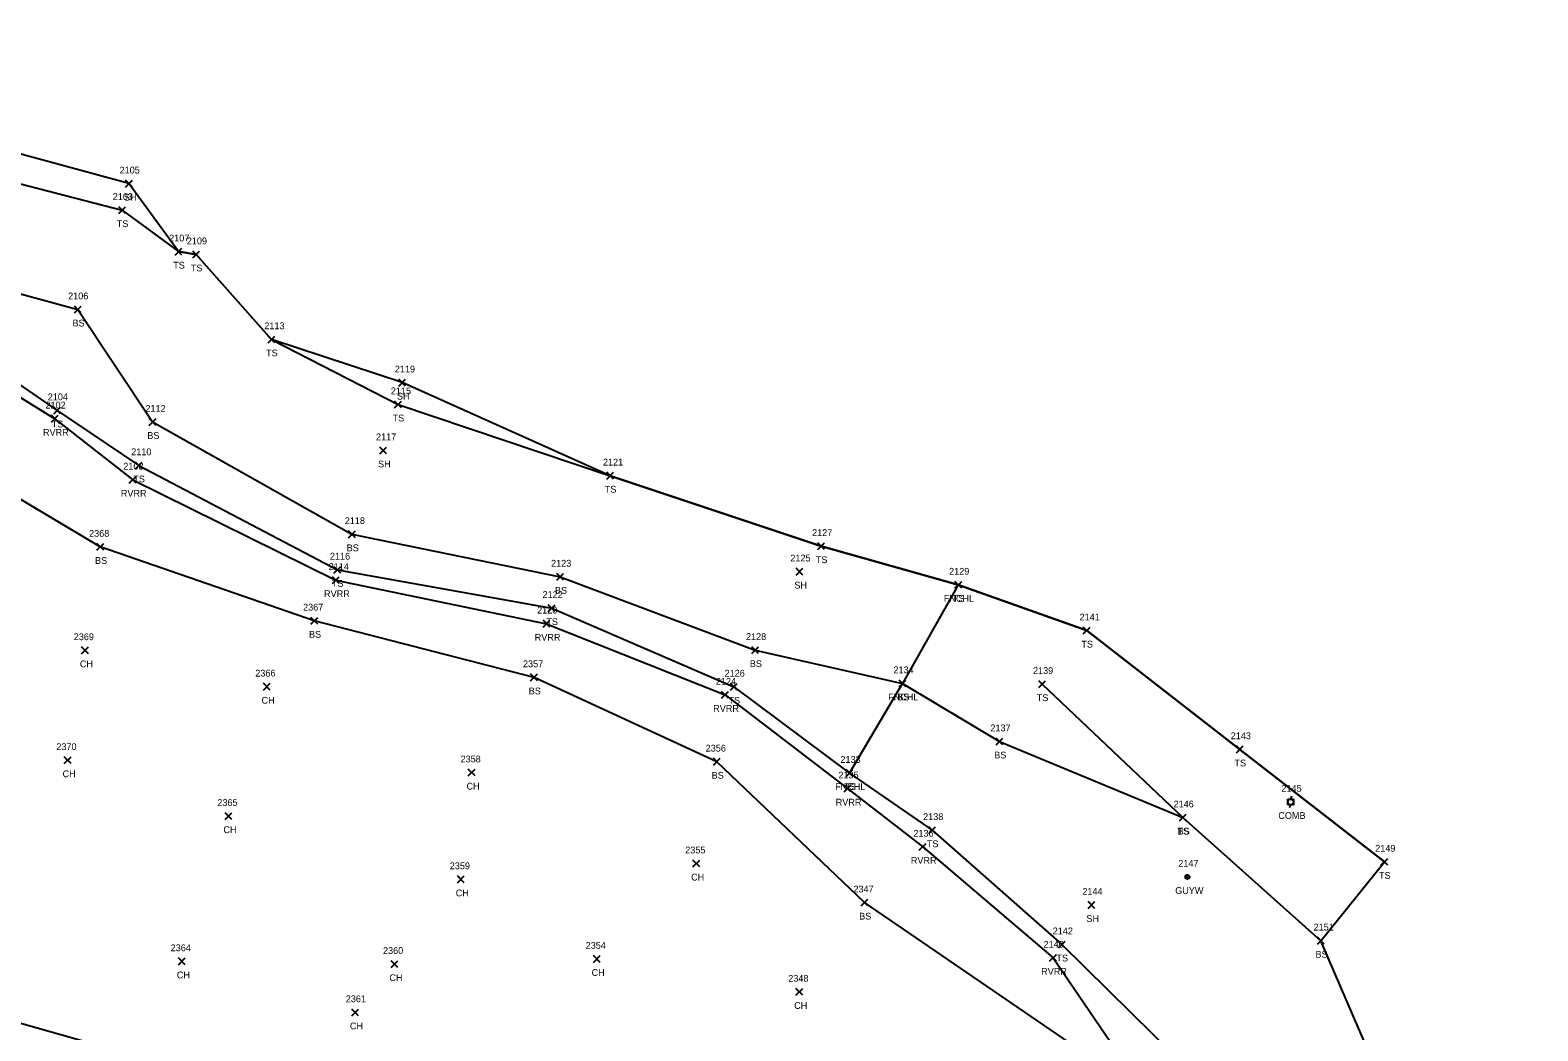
# Model space of a CAD drawing. Extents: x 1509053 to 1511576, y 400838 to 402572.
# Drawn here: x 1509430.5 to 1509874.8, y 402235 to 402530 of the extents above; entities that cross this region are included whole.
import ezdxf

# ---------------------------------------------------------------- set-up
doc = ezdxf.new("R2010")
doc.units = 0
for name, color, linetype in [('L_A', 7, 'Continuous'), ('L_I', 7, 'Continuous'), ('L_TIC', 7, 'Continuous'), ('LAWE', 7, 'Continuous'), ('LELB', 7, 'Continuous'), ('LFNC', 7, 'Continuous'), ('LSOGP', 7, 'Continuous'), ('U_A', 7, 'Continuous'), ('U_I', 7, 'Continuous'), ('UP', 7, 'Continuous'), ('UPGW', 7, 'Continuous')]:
    doc.layers.add(name, color=color, linetype=linetype)

msp = doc.modelspace()

# ---------------------------------------------------------------- linework, layer by layer
at = {"layer": 'L_TIC'}
for points in [[(1509458.59, 402483.75), (1509460.59, 402485.75)], [(1509460.59, 402483.75), (1509458.59, 402485.75)], [(1509456.58, 402475.95), (1509458.58, 402477.95)], [(1509458.58, 402475.95), (1509456.58, 402477.95)], [(1509473.2, 402463.72), (1509475.2, 402465.72)], [(1509475.2, 402463.72), (1509473.2, 402465.72)], [(1509478.41, 402462.89), (1509480.41, 402464.89)], [(1509480.41, 402462.89), (1509478.41, 402464.89)], [(1509443.49, 402446.66), (1509445.49, 402448.66)], [(1509445.49, 402446.66), (1509443.49, 402448.66)], [(1509500.59, 402437.85), (1509502.59, 402439.85)], [(1509502.59, 402437.85), (1509500.59, 402439.85)], [(1509539.07, 402425.11), (1509541.07, 402427.11)], [(1509541.07, 402425.11), (1509539.07, 402427.11)], [(1509537.87, 402418.67), (1509539.87, 402420.67)], [(1509539.87, 402418.67), (1509537.87, 402420.67)], [(1509436.74, 402414.48), (1509438.74, 402416.48)], [(1509438.74, 402414.48), (1509436.74, 402416.48)], [(1509437.42, 402416.91), (1509439.42, 402418.91)], [(1509439.42, 402416.91), (1509437.42, 402418.91)], [(1509465.55, 402413.51), (1509467.55, 402415.51)], [(1509467.55, 402413.51), (1509465.55, 402415.51)], [(1509533.51, 402405.13), (1509535.51, 402407.13)], [(1509535.51, 402405.13), (1509533.51, 402407.13)], [(1509461.46, 402400.71), (1509463.46, 402402.71)], [(1509463.46, 402400.71), (1509461.46, 402402.71)], [(1509459.68, 402396.47), (1509461.68, 402398.47)], [(1509461.68, 402396.47), (1509459.68, 402398.47)], [(1509600.4, 402397.68), (1509602.4, 402399.68)], [(1509602.4, 402397.68), (1509600.4, 402399.68)], [(1509524.3, 402380.41), (1509526.3, 402382.41)], [(1509526.3, 402380.41), (1509524.3, 402382.41)], [(1509450.14, 402376.68), (1509452.14, 402378.68)], [(1509452.14, 402376.68), (1509450.14, 402378.68)], [(1509662.58, 402376.9), (1509664.58, 402378.9)], [(1509664.58, 402376.9), (1509662.58, 402378.9)], [(1509519.99, 402369.94), (1509521.99, 402371.94)], [(1509521.99, 402369.94), (1509519.99, 402371.94)], [(1509656.17, 402369.4), (1509658.17, 402371.4)], [(1509658.17, 402369.4), (1509656.17, 402371.4)], [(1509519.56, 402366.88), (1509521.56, 402368.88)], [(1509521.56, 402366.88), (1509519.56, 402368.88)], [(1509585.66, 402367.87), (1509587.66, 402369.87)], [(1509587.66, 402367.87), (1509585.66, 402369.87)], [(1509702.97, 402365.5), (1509704.97, 402367.5)], [(1509704.97, 402365.5), (1509702.97, 402367.5)], [(1509702.97, 402365.5), (1509704.97, 402367.5)], [(1509704.97, 402365.5), (1509702.97, 402367.5)], [(1509583.16, 402358.65), (1509585.16, 402360.65)], [(1509585.16, 402358.65), (1509583.16, 402360.65)], [(1509513.2, 402354.92), (1509515.2, 402356.92)], [(1509515.2, 402354.92), (1509513.2, 402356.92)], [(1509581.65, 402354.05), (1509583.65, 402356.05)], [(1509583.65, 402354.05), (1509581.65, 402356.05)], [(1509740.81, 402352.02), (1509742.81, 402354.02)], [(1509742.81, 402352.02), (1509740.81, 402354.02)], [(1509445.62, 402346.2), (1509447.62, 402348.2)], [(1509447.62, 402346.2), (1509445.62, 402348.2)], [(1509643.11, 402346.26), (1509645.11, 402348.26)], [(1509645.11, 402346.26), (1509643.11, 402348.26)], [(1509577.95, 402338.23), (1509579.95, 402340.23)], [(1509579.95, 402338.23), (1509577.95, 402340.23)], [(1509499.18, 402335.48), (1509501.18, 402337.48)], [(1509501.18, 402335.48), (1509499.18, 402337.48)], [(1509636.85, 402335.46), (1509638.85, 402337.46)], [(1509638.85, 402335.46), (1509636.85, 402337.46)], [(1509686.55, 402336.45), (1509688.55, 402338.45)], [(1509688.55, 402336.45), (1509686.55, 402338.45)], [(1509686.55, 402336.45), (1509688.55, 402338.45)], [(1509688.55, 402336.45), (1509686.55, 402338.45)], [(1509686.55, 402336.45), (1509688.55, 402338.45)], [(1509688.55, 402336.45), (1509686.55, 402338.45)], [(1509727.69, 402336.24), (1509729.69, 402338.24)], [(1509729.69, 402336.24), (1509727.69, 402338.24)], [(1509634.23, 402333.07), (1509636.23, 402335.07)], [(1509636.23, 402333.07), (1509634.23, 402335.07)], [(1509715.12, 402319.34), (1509717.12, 402321.34)], [(1509717.12, 402319.34), (1509715.12, 402321.34)], [(1509785.94, 402317), (1509787.94, 402319.01)], [(1509787.94, 402317), (1509785.94, 402319.01)], [(1509440.53, 402313.81), (1509442.53, 402315.81)], [(1509442.53, 402313.81), (1509440.53, 402315.81)], [(1509631.84, 402313.37), (1509633.84, 402315.37)], [(1509633.84, 402313.37), (1509631.84, 402315.37)], [(1509559.56, 402310.17), (1509561.56, 402312.17)], [(1509561.56, 402310.17), (1509559.56, 402312.17)], [(1509670.92, 402310.04), (1509672.92, 402312.04)], [(1509672.92, 402310.04), (1509670.92, 402312.04)], [(1509670.92, 402310.04), (1509672.92, 402312.04)], [(1509672.92, 402310.04), (1509670.92, 402312.04)], [(1509670.34, 402305.45), (1509672.33, 402307.45)], [(1509672.33, 402305.45), (1509670.34, 402307.45)], [(1509487.94, 402297.33), (1509489.93, 402299.33)], [(1509489.93, 402297.33), (1509487.94, 402299.33)], [(1509769.14, 402296.9), (1509771.14, 402298.9)], [(1509771.14, 402296.9), (1509769.14, 402298.9)], [(1509769.14, 402296.9), (1509771.14, 402298.9)], [(1509771.14, 402296.9), (1509769.14, 402298.9)], [(1509695.29, 402293.19), (1509697.29, 402295.19)], [(1509697.29, 402293.19), (1509695.29, 402295.19)], [(1509692.47, 402288.28), (1509694.47, 402290.28)], [(1509694.47, 402288.28), (1509692.47, 402290.28)], [(1509625.76, 402283.35), (1509627.76, 402285.35)], [(1509627.76, 402283.35), (1509625.76, 402285.35)], [(1509828.53, 402283.86), (1509830.53, 402285.86)], [(1509830.53, 402283.86), (1509828.53, 402285.86)], [(1509556.39, 402278.69), (1509558.39, 402280.69)], [(1509558.39, 402278.69), (1509556.39, 402280.69)], [(1509675.33, 402271.85), (1509677.33, 402273.85)], [(1509677.33, 402271.85), (1509675.33, 402273.85)], [(1509742.22, 402271.14), (1509744.22, 402273.14)], [(1509744.22, 402271.14), (1509742.22, 402273.14)], [(1509733.48, 402259.5), (1509735.48, 402261.5)], [(1509735.48, 402259.5), (1509733.48, 402261.5)], [(1509809.8, 402260.62), (1509811.8, 402262.62)], [(1509811.8, 402260.62), (1509809.8, 402262.62)], [(1509474.19, 402254.52), (1509476.19, 402256.52)], [(1509476.19, 402254.52), (1509474.19, 402256.52)], [(1509536.84, 402253.72), (1509538.84, 402255.72)], [(1509538.84, 402253.72), (1509536.84, 402255.72)], [(1509596.43, 402255.24), (1509598.43, 402257.24)], [(1509598.43, 402255.24), (1509596.43, 402257.24)], [(1509730.88, 402255.56), (1509732.88, 402257.56)], [(1509732.88, 402255.56), (1509730.88, 402257.56)], [(1509656.12, 402245.53), (1509658.12, 402247.53)], [(1509658.12, 402245.53), (1509656.12, 402247.53)], [(1509525.21, 402239.48), (1509527.21, 402241.48)], [(1509527.21, 402239.48), (1509525.21, 402241.48)]]:
    msp.add_lwpolyline(points, dxfattribs=at)
at = {"layer": 'LAWE'}
msp.add_lwpolyline([(1509123.74, 402492.84), (1509257.15, 402479.28), (1509295.46, 402474.2), (1509323.52, 402463.27), (1509340.74, 402459.51), (1509387.7, 402446.48), (1509437.74, 402415.48), (1509460.68, 402397.47), (1509520.56, 402367.88), (1509582.65, 402355.05), (1509635.23, 402334.07), (1509671.33, 402306.45), (1509693.48, 402289.28), (1509731.88, 402256.56), (1509764.07, 402209.44), (1509800.56, 402171.69), (1509807.78, 402147.71), (1509842.98, 402079.8), (1509863.82, 402015.71), (1509885.9, 401967.01)], dxfattribs=at)
at = {"layer": 'LELB'}
for points in [[(1509115.54, 402530), (1509210.25, 402526.55), (1509259.04, 402514.59), (1509304.29, 402509.73), (1509334.97, 402505.2), (1509343.55, 402508.97), (1509356.02, 402506.81), (1509405.08, 402490.51), (1509457.58, 402476.95), (1509474.2, 402464.72), (1509479.41, 402463.89), (1509501.59, 402438.85), (1509538.87, 402419.67), (1509601.4, 402398.68), (1509663.58, 402377.9), (1509703.97, 402366.5), (1509741.81, 402353.02), (1509786.94, 402318.01), (1509829.53, 402284.86)], [(1510159.39, 401957.43), (1510109.97, 401933.78), (1510073.83, 401925.83), (1510030.04, 401920.72), (1509978.38, 401922.31), (1509938.9, 401925.26), (1509910.2, 401929.61), (1509860.63, 401969.45), (1509838.12, 402012.73), (1509801.23, 402094.39), (1509783.45, 402152.2), (1509742.56, 402227.61), (1509676.33, 402272.85), (1509632.84, 402314.37), (1509578.95, 402339.23), (1509514.2, 402355.92), (1509451.14, 402377.68), (1509400.45, 402407.85), (1509346.01, 402449.55), (1509331.23, 402458.28), (1509283.72, 402454.96), (1509188.27, 402469.29), (1509186.96, 402469.12), (1509142.12, 402468.65)], [(1509347.55, 402467.93), (1509400.56, 402459.64), (1509444.49, 402447.66), (1509466.55, 402414.51), (1509525.3, 402381.4), (1509586.66, 402368.88), (1509644.11, 402347.26), (1509687.55, 402337.45), (1509716.12, 402320.34), (1509770.15, 402297.9), (1509810.8, 402261.62)], [(1509342.35, 402460.5), (1509388.98, 402451.84), (1509438.42, 402417.91), (1509462.47, 402401.71), (1509520.99, 402370.94), (1509584.16, 402359.65), (1509637.85, 402336.46), (1509671.92, 402311.04), (1509696.29, 402294.18), (1509734.49, 402260.5), (1509774.99, 402220.64)], [(1509893.6, 401622.33), (1509860.64, 401660.7), (1509835.46, 401719.88), (1509820.45, 401775.67), (1509804.55, 401821.18), (1509793.58, 401877.47), (1509769.39, 401921.13), (1509750.31, 401995.31), (1509714.67, 402043.06), (1509675.87, 402101.28), (1509636.96, 402136.16), (1509603.47, 402183.37), (1509565.38, 402200.63), (1509506.19, 402219.72), (1509454.31, 402229.61), (1509409.3, 402242.42), (1509343.87, 402268.78), (1509286.85, 402299.31), (1509229.32, 402329.05), (1509168.38, 402334.88), (1509111.42, 402354.71)], [(1509728.69, 402337.24), (1509770.15, 402297.9)]]:
    msp.add_lwpolyline(points, dxfattribs=at)
at = {"layer": 'LFNC'}
for points in [[(1509703.97, 402366.5), (1509687.55, 402337.45)], [(1509671.92, 402311.04), (1509687.55, 402337.45)]]:
    msp.add_lwpolyline(points, dxfattribs=at)
at = {"layer": 'LSOGP'}
msp.add_lwpolyline([(1509886.95, 402120.34), (1509847.82, 402175.09), (1509849.39, 402190.96), (1509846.35, 402196.04), (1509831.65, 402213.38), (1509810.8, 402261.62), (1509829.53, 402284.86), (1509786.94, 402318.01), (1509741.81, 402353.02), (1509703.97, 402366.5), (1509663.58, 402377.9), (1509601.4, 402398.68), (1509540.06, 402426.11), (1509501.59, 402438.85), (1509479.41, 402463.89), (1509474.2, 402464.72), (1509459.59, 402484.75), (1509407.76, 402498.88)], dxfattribs=at)
at = {"layer": 'UP'}
for p, q in [((1509802.15, 402304.18), (1509801.9, 402303.35)), ((1509801.06, 402301.68), (1509801.06, 402303.35)), ((1509801.06, 402303.35), (1509802.73, 402303.35)), ((1509802.73, 402301.68), (1509801.06, 402301.68)), ((1509801.65, 402300.85), (1509801.9, 402301.68)), ((1509801.9, 402302.52), (1509801.9, 402302.52)), ((1509802.73, 402303.35), (1509802.73, 402301.68))]:
    msp.add_line(p, q, dxfattribs=at)
msp.add_circle((1509801.9, 402302.52), 0.833, dxfattribs=at)
at = {"layer": 'UPGW'}
for radius in [0.625, 0.0833]:
    msp.add_circle((1509771.5, 402280.41), radius, dxfattribs=at)

# ---------------------------------------------------------------- texts
at = {"layer": 'L_A'}
for s, p in [('SH', (1509458.08, 402479.75)), ('TS', (1509455.99, 402471.95)), ('TS', (1509472.61, 402459.72)), ('TS', (1509477.82, 402458.89)), ('BS', (1509442.93, 402442.66)), ('TS', (1509500, 402433.85)), ('SH', (1509538.55, 402421.11)), ('TS', (1509537.28, 402414.67)), ('RVRR', (1509434.25, 402410.48)), ('TS', (1509436.83, 402412.91)), ('BS', (1509464.99, 402409.51)), ('SH', (1509533, 402401.12)), ('TS', (1509460.87, 402396.71)), ('RVRR', (1509457.19, 402392.47)), ('TS', (1509599.81, 402393.68)), ('BS', (1509523.74, 402376.41)), ('BS', (1509449.58, 402372.68)), ('TS', (1509661.99, 402372.9)), ('TS', (1509519.4, 402365.94)), ('SH', (1509655.66, 402365.4)), ('RVRR', (1509517.08, 402362.88)), ('BS', (1509585.1, 402363.87)), ('FNCHL', (1509699.72, 402361.5)), ('TS', (1509702.38, 402361.5)), ('TS', (1509582.57, 402354.65)), ('BS', (1509512.64, 402350.92)), ('RVRR', (1509579.16, 402350.05)), ('TS', (1509740.22, 402348.02)), ('CH', (1509445.11, 402342.2)), ('BS', (1509642.55, 402342.26)), ('BS', (1509577.39, 402334.23)), ('CH', (1509498.66, 402331.48)), ('RVRR', (1509631.75, 402329.07)), ('TS', (1509636.26, 402331.46)), ('FNCHL', (1509683.3, 402332.45)), ('FNCHL', (1509683.3, 402332.45)), ('BS', (1509685.99, 402332.45)), ('TS', (1509727.1, 402332.24)), ('BS', (1509714.56, 402315.34)), ('TS', (1509785.35, 402313)), ('CH', (1509440.02, 402309.81)), ('BS', (1509631.28, 402309.37)), ('CH', (1509559.05, 402306.17)), ('FNCHL', (1509667.67, 402306.04)), ('TS', (1509670.33, 402306.04)), ('RVRR', (1509667.85, 402301.45)), ('CH', (1509487.42, 402293.33)), ('TS', (1509694.7, 402289.18)), ('TS', (1509768.55, 402292.9)), ('BS', (1509768.59, 402292.9)), ('RVRR', (1509689.99, 402284.28)), ('CH', (1509625.24, 402279.35)), ('TS', (1509827.94, 402279.86)), ('CH', (1509555.88, 402274.69)), ('BS', (1509674.77, 402267.85)), ('SH', (1509741.71, 402267.14)), ('TS', (1509732.89, 402255.5)), ('BS', (1509809.24, 402256.62)), ('CH', (1509473.68, 402250.52)), ('CH', (1509536.33, 402249.72)), ('CH', (1509595.92, 402251.24)), ('RVRR', (1509728.39, 402251.56)), ('CH', (1509655.61, 402241.53)), ('CH', (1509524.7, 402235.48))]:
    msp.add_text(s, height=2, dxfattribs=at).set_placement(p)
at = {"layer": 'L_I'}
for s, p in [('2105', (1509456.82, 402487.75)), ('2103', (1509454.81, 402479.95)), ('2107', (1509471.43, 402467.72)), ('2109', (1509476.63, 402466.89)), ('2106', (1509441.66, 402450.66)), ('2113', (1509499.47, 402441.85)), ('2119', (1509537.93, 402429.11)), ('2115', (1509536.75, 402422.67)), ('2102', (1509434.97, 402418.48)), ('2104', (1509435.65, 402420.91)), ('2112', (1509464.43, 402417.51)), ('2117', (1509532.39, 402409.12)), ('2110', (1509460.25, 402404.71)), ('2108', (1509457.91, 402400.47)), ('2121', (1509599.27, 402401.68)), ('2118', (1509523.17, 402384.41)), ('2368', (1509447.83, 402380.68)), ('2127', (1509660.88, 402380.9)), ('2116', (1509518.81, 402373.94)), ('2125', (1509654.48, 402373.4)), ('2114', (1509518.44, 402370.88)), ('2123', (1509583.97, 402371.87)), ('2129', (1509701.27, 402369.5)), ('2129', (1509701.27, 402369.5)), ('2122', (1509581.47, 402362.65)), ('2367', (1509510.89, 402358.92)), ('2120', (1509579.87, 402358.05)), ('2141', (1509739.69, 402356.02)), ('2369', (1509443.31, 402350.2)), ('2128', (1509641.42, 402350.26)), ('2357', (1509575.69, 402342.23)), ('2366', (1509496.81, 402339.48)), ('2126', (1509635.1, 402339.46)), ('2134', (1509684.86, 402340.45)), ('2134', (1509684.86, 402340.45)), ('2134', (1509684.86, 402340.45)), ('2139', (1509725.99, 402340.24)), ('2124', (1509632.54, 402337.07)), ('2137', (1509713.43, 402323.34)), ('2143', (1509784.25, 402321.01)), ('2370', (1509438.19, 402317.81)), ('2356', (1509629.53, 402317.37)), ('2358', (1509557.3, 402314.17)), ('2133', (1509669.23, 402314.04)), ('2133', (1509669.23, 402314.04)), ('2135', (1509668.64, 402309.45)), ('2365', (1509485.63, 402301.33)), ('2146', (1509767.4, 402300.9)), ('2146', (1509767.4, 402300.9)), ('2138', (1509693.6, 402297.18)), ('2136', (1509690.73, 402292.28)), ('2355', (1509623.5, 402287.35)), ('2149', (1509826.83, 402287.86)), ('2359', (1509554.12, 402282.69)), ('2347', (1509673.07, 402275.85)), ('2144', (1509740.53, 402275.14)), ('2142', (1509731.79, 402263.5)), ('2151', (1509808.67, 402264.62)), ('2364', (1509471.88, 402258.52)), ('2360', (1509534.45, 402257.72)), ('2354', (1509594.17, 402259.24)), ('2140', (1509729.1, 402259.56)), ('2348', (1509653.86, 402249.53)), ('2361', (1509523.47, 402243.48))]:
    msp.add_text(s, height=2, dxfattribs=at).set_placement(p)
at = {"layer": 'U_A'}
for s, p in [('COMB', (1509798.28, 402297.52)), ('GUYW', (1509767.89, 402275.41))]:
    msp.add_text(s, height=2, dxfattribs=at).set_placement(p)
at = {"layer": 'U_I'}
for s, p in [('2145', (1509799.2, 402305.52)), ('2147', (1509768.81, 402283.41))]:
    msp.add_text(s, height=2, dxfattribs=at).set_placement(p)

doc.saveas('drawing.dxf')
